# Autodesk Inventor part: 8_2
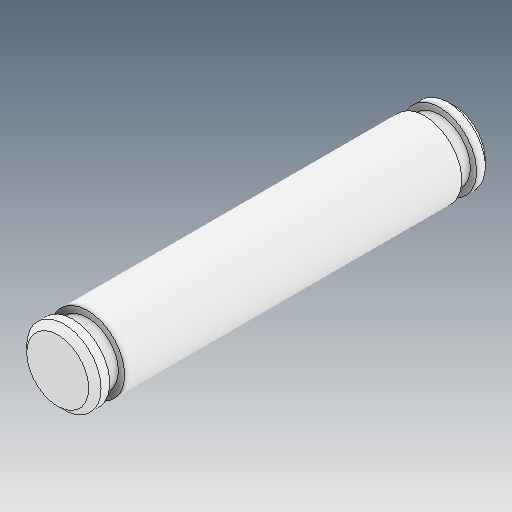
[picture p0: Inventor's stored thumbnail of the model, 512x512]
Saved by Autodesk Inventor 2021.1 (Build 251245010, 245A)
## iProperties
Created: 2021-06
Part Number: 8_2
Material: Ogólny
Document SubType Name: Modeling
Designer: user
Density: 1 g/cm^3
Appearance: Domyślna
Author: user
Revision Number: ÈÎºÎ
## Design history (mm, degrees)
feature "ÊäÈë1"
node "Bryła1"
